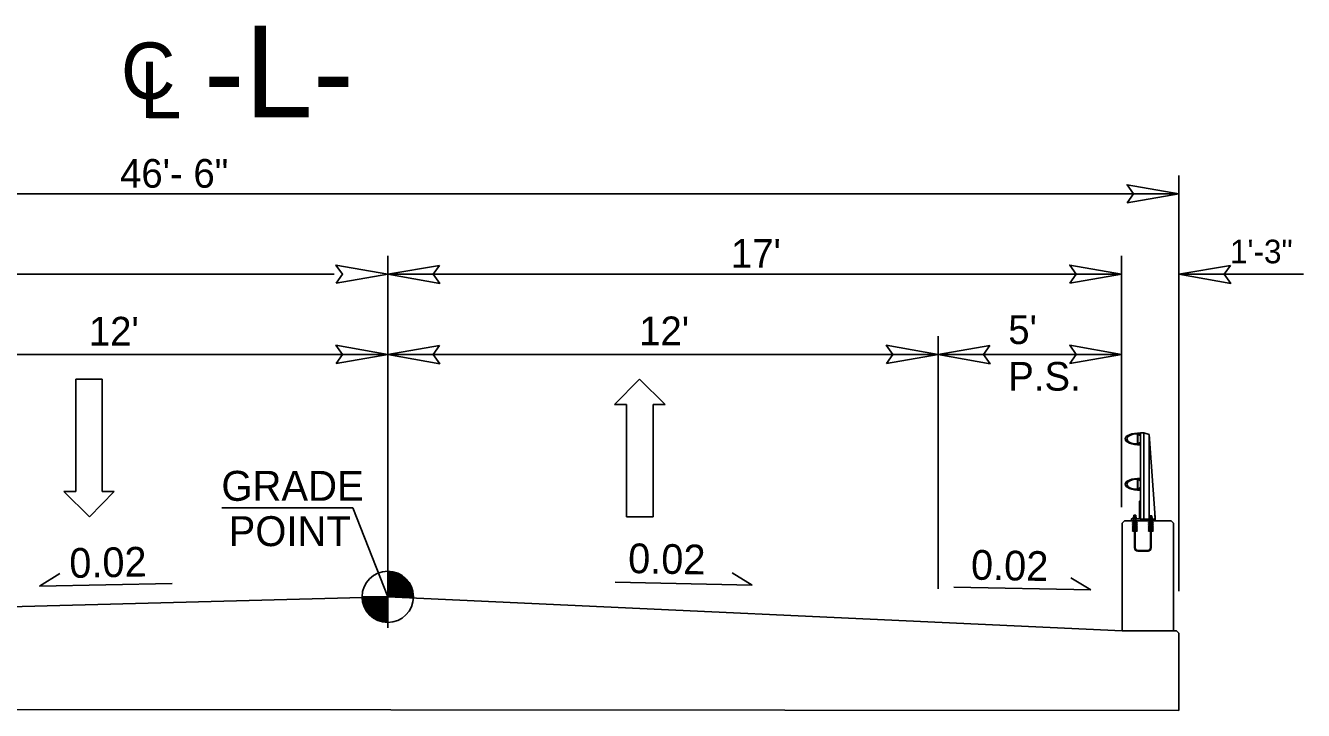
# Model space of a CAD drawing. Extents: x 1733676 to 1734289, y 540979 to 541226.
# Drawn here: x 1733769.65 to 1733797.52, y 541034.32 to 541049.26 of the extents above; entities that cross this region are included whole.
import ezdxf

# ---------------------------------------------------------------- set-up
doc = ezdxf.new("R2010")
doc.units = 0
for name, color, linetype in [('Prop Dimension', 7, 'Continuous'), ('Prop Lane Arrow CELL', 7, 'Continuous'), ('Prop Terminator CELL', 7, 'Continuous'), ('Typical Bridge Rail Two Bar CELL', 7, 'Continuous'), ('Typical Grade Point Symbol CELL', 7, 'Continuous'), ('Typical Pavement Slope CELL', 7, 'Continuous'), ('Typical Pavement Slope Information CELL', 7, 'Continuous'), ('Typical Slope Point Local CELL', 7, 'Continuous'), ('Typical Text Centerline CELL', 7, 'Continuous'), ('Typical Text Grade Point CELL', 7, 'Continuous')]:
    doc.layers.add(name, color=color, linetype=linetype)

msp = doc.modelspace()

# ---------------------------------------------------------------- linework, layer by layer
at = {"layer": 'Prop Dimension'}
for p, q in [((1733794.804, 541036.923), (1733794.804, 541045.985)), ((1733794.804, 541045.585), (1733749.804, 541045.585)), ((1733777.554, 541036.129), (1733777.554, 541044.235)), ((1733793.554, 541038.756), (1733793.554, 541044.235)), ((1733776.387, 541043.835), (1733760.554, 541043.835)), ((1733793.554, 541043.835), (1733777.554, 541043.835)), ((1733794.804, 541043.835), (1733797.519, 541043.835)), ((1733789.554, 541036.979), (1733789.554, 541042.485)), ((1733777.554, 541042.085), (1733765.554, 541042.085)), ((1733789.554, 541042.085), (1733777.554, 541042.085)), ((1733793.554, 541042.085), (1733789.554, 541042.085)), ((1733773.933, 541038.739), (1733776.793, 541038.739)), ((1733777.554, 541036.801), (1733776.793, 541038.739))]:
    msp.add_line(p, q, dxfattribs=at)
at = {"layer": 'Prop Lane Arrow CELL'}
for p, q in [((1733770.75, 541039.095), (1733770.75, 541041.545)), ((1733770.75, 541041.545), (1733771.327, 541041.545)), ((1733771.327, 541041.545), (1733771.327, 541039.095)), ((1733782.497, 541040.994), (1733783.04, 541041.545)), ((1733783.04, 541041.545), (1733783.6, 541040.994)), ((1733782.76, 541040.994), (1733782.497, 541040.994)), ((1733782.76, 541038.544), (1733782.76, 541040.994)), ((1733783.6, 541040.994), (1733783.337, 541040.994)), ((1733783.337, 541040.994), (1733783.337, 541038.544)), ((1733771.047, 541038.544), (1733770.487, 541039.095)), ((1733770.487, 541039.095), (1733770.75, 541039.095)), ((1733771.59, 541039.095), (1733771.047, 541038.544)), ((1733771.327, 541039.095), (1733771.59, 541039.095)), ((1733783.337, 541038.544), (1733782.76, 541038.544))]:
    msp.add_line(p, q, dxfattribs=at)
at = {"layer": 'Prop Terminator CELL'}
for points in [[(1733793.679, 541045.391), (1733794.804, 541045.585), (1733793.673, 541045.785), (1733793.816, 541045.585)], [(1733776.429, 541043.641), (1733777.554, 541043.835), (1733776.423, 541044.035), (1733776.566, 541043.835)], [(1733778.679, 541044.029), (1733777.554, 541043.835), (1733778.685, 541043.635), (1733778.541, 541043.835)], [(1733792.429, 541043.641), (1733793.554, 541043.835), (1733792.423, 541044.035), (1733792.566, 541043.835)], [(1733795.929, 541044.029), (1733794.804, 541043.835), (1733795.935, 541043.635), (1733795.791, 541043.835)], [(1733776.429, 541041.891), (1733777.554, 541042.085), (1733776.423, 541042.285), (1733776.566, 541042.085)], [(1733778.679, 541042.279), (1733777.554, 541042.085), (1733778.685, 541041.885), (1733778.541, 541042.085)], [(1733788.429, 541041.891), (1733789.554, 541042.085), (1733788.423, 541042.285), (1733788.566, 541042.085)], [(1733790.679, 541042.279), (1733789.554, 541042.085), (1733790.685, 541041.885), (1733790.541, 541042.085)], [(1733792.429, 541041.891), (1733793.554, 541042.085), (1733792.423, 541042.285), (1733792.566, 541042.085)]]:
    msp.add_lwpolyline(points, close=True, dxfattribs=at)
at = {"layer": 'Typical Bridge Rail Two Bar CELL'}
for p, q in [((1733793.901, 541040.346), (1733793.901, 541040.244)), ((1733793.964, 541040.377), (1733794.04, 541040.377)), ((1733793.964, 541038.494), (1733793.964, 541040.377)), ((1733794.154, 541040.34), (1733794.04, 541040.377)), ((1733794.04, 541038.494), (1733794.04, 541040.377)), ((1733794.154, 541038.494), (1733794.154, 541040.34)), ((1733794.154, 541040.34), (1733794.285, 541038.531)), ((1733793.901, 541040.141), (1733793.901, 541040.244)), ((1733793.901, 541039.359), (1733793.901, 541039.256)), ((1733793.901, 541039.154), (1733793.901, 541039.256)), ((1733794.154, 541039.476), (1733794.158, 541039.476)), ((1733793.615, 541038.456), (1733793.566, 541038.407)), ((1733793.566, 541038.407), (1733793.566, 541036.062)), ((1733793.615, 541038.456), (1733794.635, 541038.456)), ((1733793.793, 541038.42), (1733793.893, 541038.42)), ((1733793.793, 541038.409), (1733793.893, 541038.409)), ((1733793.793, 541038.375), (1733793.835, 541038.375)), ((1733793.793, 541038.364), (1733793.835, 541038.364)), ((1733793.815, 541038.397), (1733793.835, 541038.397)), ((1733793.815, 541038.386), (1733793.835, 541038.386)), ((1733793.818, 541038.42), (1733793.818, 541038.503)), ((1733793.82, 541038.544), (1733793.82, 541038.58)), ((1733793.82, 541038.58), (1733793.863, 541038.58)), ((1733793.835, 541038.398), (1733793.835, 541037.867)), ((1733793.835, 541038.397), (1733793.851, 541038.397)), ((1733793.851, 541038.398), (1733793.851, 541037.867)), ((1733793.851, 541038.397), (1733793.871, 541038.397)), ((1733793.851, 541038.386), (1733793.871, 541038.386)), ((1733793.851, 541038.375), (1733793.893, 541038.375)), ((1733793.851, 541038.364), (1733793.893, 541038.364)), ((1733793.863, 541038.58), (1733793.863, 541038.544)), ((1733793.865, 541038.42), (1733793.865, 541038.503)), ((1733794.141, 541038.42), (1733794.242, 541038.42)), ((1733794.141, 541038.409), (1733794.242, 541038.409)), ((1733794.141, 541038.375), (1733794.183, 541038.375)), ((1733794.141, 541038.364), (1733794.183, 541038.364)), ((1733794.164, 541038.397), (1733794.183, 541038.397)), ((1733794.164, 541038.386), (1733794.183, 541038.386)), ((1733794.169, 541038.534), (1733794.169, 541038.57)), ((1733794.169, 541038.57), (1733794.212, 541038.57)), ((1733794.169, 541038.41), (1733794.169, 541038.494)), ((1733794.183, 541038.398), (1733794.2, 541038.398)), ((1733794.183, 541038.398), (1733794.183, 541037.867)), ((1733794.2, 541038.398), (1733794.2, 541037.867)), ((1733794.2, 541038.397), (1733794.22, 541038.397)), ((1733794.2, 541038.386), (1733794.22, 541038.386)), ((1733794.2, 541038.375), (1733794.242, 541038.375)), ((1733794.2, 541038.364), (1733794.242, 541038.364)), ((1733794.212, 541038.57), (1733794.212, 541038.534)), ((1733794.213, 541038.41), (1733794.213, 541038.494)), ((1733794.282, 541038.552), (1733794.282, 541038.585)), ((1733794.285, 541038.494), (1733794.285, 541038.531)), ((1733794.684, 541038.407), (1733794.635, 541038.456)), ((1733794.684, 541038.407), (1733794.684, 541036.062)), ((1733793.793, 541038.331), (1733793.835, 541038.331)), ((1733793.793, 541038.319), (1733793.835, 541038.319)), ((1733793.793, 541038.286), (1733793.835, 541038.286)), ((1733793.793, 541038.275), (1733793.835, 541038.275)), ((1733793.793, 541038.242), (1733793.835, 541038.242)), ((1733793.793, 541038.231), (1733793.835, 541038.231)), ((1733793.815, 541038.353), (1733793.835, 541038.353)), ((1733793.815, 541038.342), (1733793.835, 541038.342)), ((1733793.815, 541038.308), (1733793.835, 541038.308)), ((1733793.815, 541038.297), (1733793.835, 541038.297)), ((1733793.815, 541038.264), (1733793.835, 541038.264)), ((1733793.815, 541038.253), (1733793.835, 541038.253)), ((1733793.851, 541038.353), (1733793.871, 541038.353)), ((1733793.851, 541038.342), (1733793.871, 541038.342)), ((1733793.851, 541038.331), (1733793.893, 541038.331)), ((1733793.851, 541038.319), (1733793.893, 541038.319)), ((1733793.851, 541038.308), (1733793.871, 541038.308)), ((1733793.851, 541038.297), (1733793.871, 541038.297)), ((1733793.851, 541038.286), (1733793.893, 541038.286)), ((1733793.851, 541038.275), (1733793.893, 541038.275)), ((1733793.851, 541038.264), (1733793.871, 541038.264)), ((1733793.851, 541038.253), (1733793.871, 541038.253)), ((1733793.851, 541038.242), (1733793.893, 541038.242)), ((1733793.851, 541038.231), (1733793.893, 541038.231)), ((1733794.141, 541038.331), (1733794.183, 541038.331)), ((1733794.141, 541038.319), (1733794.183, 541038.319)), ((1733794.141, 541038.286), (1733794.183, 541038.286)), ((1733794.141, 541038.275), (1733794.183, 541038.275)), ((1733794.141, 541038.242), (1733794.183, 541038.242)), ((1733794.141, 541038.231), (1733794.183, 541038.231)), ((1733794.164, 541038.353), (1733794.183, 541038.353)), ((1733794.164, 541038.342), (1733794.183, 541038.342)), ((1733794.164, 541038.308), (1733794.183, 541038.308)), ((1733794.164, 541038.297), (1733794.183, 541038.297)), ((1733794.164, 541038.264), (1733794.183, 541038.264)), ((1733794.164, 541038.253), (1733794.183, 541038.253)), ((1733794.2, 541038.353), (1733794.22, 541038.353)), ((1733794.2, 541038.342), (1733794.22, 541038.342)), ((1733794.2, 541038.331), (1733794.242, 541038.331)), ((1733794.2, 541038.319), (1733794.242, 541038.319)), ((1733794.2, 541038.308), (1733794.22, 541038.308)), ((1733794.2, 541038.297), (1733794.22, 541038.297)), ((1733794.2, 541038.286), (1733794.242, 541038.286)), ((1733794.2, 541038.275), (1733794.242, 541038.275)), ((1733794.2, 541038.264), (1733794.22, 541038.264)), ((1733794.2, 541038.253), (1733794.22, 541038.253)), ((1733794.2, 541038.242), (1733794.242, 541038.242)), ((1733794.2, 541038.231), (1733794.242, 541038.231)), ((1733793.905, 541037.814), (1733794.13, 541037.814)), ((1733793.905, 541037.797), (1733794.13, 541037.797)), ((1733793.566, 541036.062), (1733794.674, 541036.062)), ((1733794.674, 541036.062), (1733794.755, 541036.062)), ((1733794.804, 541036.009), (1733794.755, 541036.062))]:
    msp.add_line(p, q, dxfattribs=at)
for points in [[(1733793.964, 541040.113), (1733793.964, 541040.162), (1733793.944, 541040.162), (1733793.944, 541040.154), (1733793.946, 541040.154), (1733793.946, 541040.133), (1733793.914, 541040.133), (1733793.91, 541040.165), (1733793.91, 541040.244), (1733793.91, 541040.322), (1733793.914, 541040.354), (1733793.946, 541040.354), (1733793.946, 541040.333), (1733793.944, 541040.333), (1733793.944, 541040.325), (1733793.964, 541040.325), (1733793.964, 541040.374)], [(1733793.964, 541039.126), (1733793.964, 541039.175), (1733793.944, 541039.175), (1733793.944, 541039.167), (1733793.946, 541039.167), (1733793.946, 541039.146), (1733793.914, 541039.146), (1733793.91, 541039.178), (1733793.91, 541039.256), (1733793.91, 541039.335), (1733793.914, 541039.366), (1733793.946, 541039.366), (1733793.946, 541039.346), (1733793.944, 541039.346), (1733793.944, 541039.338), (1733793.964, 541039.338), (1733793.964, 541039.387)], [(1733793.771, 541038.456), (1733793.771, 541038.503), (1733793.946, 541038.503), (1733793.946, 541038.89), (1733793.964, 541038.89), (1733793.964, 541038.494), (1733794.276, 541038.494), (1733794.276, 541038.521), (1733794.285, 541038.521), (1733794.285, 541038.456), (1733794.135, 541038.456), (1733794.135, 541038.482), (1733793.983, 541038.482), (1733793.983, 541038.456), (1733793.771, 541038.456)], [(1733793.793, 541038.42), (1733793.793, 541038.409), (1733793.815, 541038.397), (1733793.815, 541038.386), (1733793.793, 541038.375), (1733793.793, 541038.364), (1733793.815, 541038.353), (1733793.815, 541038.342), (1733793.793, 541038.331), (1733793.793, 541038.319), (1733793.815, 541038.308), (1733793.815, 541038.297), (1733793.793, 541038.286), (1733793.793, 541038.275), (1733793.815, 541038.264), (1733793.815, 541038.253), (1733793.793, 541038.242), (1733793.793, 541038.231)], [(1733793.798, 541038.503), (1733793.798, 541038.511), (1733793.841, 541038.511), (1733793.884, 541038.511), (1733793.884, 541038.503)], [(1733793.81, 541038.511), (1733793.81, 541038.538), (1733793.815, 541038.544), (1733793.868, 541038.544), (1733793.873, 541038.538), (1733793.873, 541038.511), (1733793.81, 541038.511), (1733793.831, 541038.511), (1733793.831, 541038.538), (1733793.826, 541038.544), (1733793.831, 541038.538), (1733793.836, 541038.544), (1733793.847, 541038.544), (1733793.852, 541038.538), (1733793.852, 541038.511), (1733793.852, 541038.538), (1733793.857, 541038.544)], [(1733793.893, 541038.42), (1733793.893, 541038.409), (1733793.871, 541038.397), (1733793.871, 541038.386), (1733793.893, 541038.375), (1733793.893, 541038.364), (1733793.871, 541038.353), (1733793.871, 541038.342), (1733793.893, 541038.331), (1733793.893, 541038.319), (1733793.871, 541038.308), (1733793.871, 541038.297), (1733793.893, 541038.286), (1733793.893, 541038.275), (1733793.871, 541038.264), (1733793.871, 541038.253), (1733793.893, 541038.242), (1733793.893, 541038.231)], [(1733794.141, 541038.42), (1733794.141, 541038.409), (1733794.163, 541038.397), (1733794.163, 541038.386), (1733794.141, 541038.375), (1733794.141, 541038.364), (1733794.163, 541038.353), (1733794.163, 541038.342), (1733794.141, 541038.331), (1733794.141, 541038.319), (1733794.163, 541038.308), (1733794.163, 541038.297), (1733794.141, 541038.286), (1733794.141, 541038.275), (1733794.163, 541038.264), (1733794.163, 541038.253), (1733794.141, 541038.242), (1733794.141, 541038.231)], [(1733794.148, 541038.493), (1733794.148, 541038.502), (1733794.191, 541038.502), (1733794.233, 541038.502), (1733794.233, 541038.493)], [(1733794.159, 541038.502), (1733794.159, 541038.529), (1733794.164, 541038.534), (1733794.217, 541038.534), (1733794.222, 541038.529), (1733794.222, 541038.502), (1733794.159, 541038.502), (1733794.18, 541038.502), (1733794.18, 541038.529), (1733794.175, 541038.534), (1733794.18, 541038.529), (1733794.185, 541038.534), (1733794.196, 541038.534), (1733794.201, 541038.529), (1733794.201, 541038.502), (1733794.201, 541038.529), (1733794.207, 541038.534)], [(1733794.242, 541038.42), (1733794.242, 541038.409), (1733794.22, 541038.397), (1733794.22, 541038.386), (1733794.242, 541038.375), (1733794.242, 541038.364), (1733794.22, 541038.353), (1733794.22, 541038.342), (1733794.242, 541038.331), (1733794.242, 541038.319), (1733794.22, 541038.308), (1733794.22, 541038.297), (1733794.242, 541038.286), (1733794.242, 541038.275), (1733794.22, 541038.264), (1733794.22, 541038.253), (1733794.242, 541038.242), (1733794.242, 541038.231)]]:
    msp.add_lwpolyline(points, dxfattribs=at)
for centre in [(1733793.802, 541038.259), (1733794.233, 541038.259)]:
    msp.add_circle(centre, 0.00834, dxfattribs=at)
for centre, radius, start, end in [((1733793.894, 541040.346), 0.00783, 0, 90), ((1733793.894, 541040.141), 0.00783, 270, 0), ((1733793.894, 541039.359), 0.00783, 0, 90), ((1733793.894, 541039.154), 0.00783, 270, 0), ((1733793.905, 541037.867), 0.07, 180, 270), ((1733793.905, 541037.867), 0.0534, 180, 270), ((1733794.13, 541037.867), 0.0534, 270, 0), ((1733794.13, 541037.867), 0.07, 270, 0)]:
    msp.add_arc(centre, radius, start, end, dxfattribs=at)
for centre, major_axis, ratio, start_param, end_param in [((1733793.965, 541040.244), (-0.334, 0), 0.39036, 4.712404, 6.283584), ((1733793.894, 541040.244), (-0.222, 0), 0.495501, 4.712489, 6.283652), ((1733793.965, 541040.244), (-0.334, 0), 0.39036, 0.000398, 1.570782), ((1733793.894, 541040.244), (-0.222, 0), 0.495501, 0.000467, 1.570696), ((1733793.965, 541039.256), (-0.334, 0), 0.39036, 4.712404, 6.283584), ((1733793.965, 541039.256), (-0.334, 0), 0.39036, 0.000398, 1.570782), ((1733793.894, 541039.256), (-0.222, 0), 0.495501, 4.712489, 6.283652), ((1733793.894, 541039.256), (-0.222, 0), 0.495501, 0.000467, 1.570696)]:
    msp.add_ellipse(centre, major_axis=major_axis, ratio=ratio, start_param=start_param, end_param=end_param, dxfattribs=at)
at = {"layer": 'Typical Grade Point Symbol CELL'}
for p, q in [((1733777.554, 541036.801), (1733777.554, 541037.361)), ((1733776.994, 541036.801), (1733777.554, 541036.801)), ((1733777.553, 541036.242), (1733777.554, 541036.801)), ((1733777.554, 541036.801), (1733777.553, 541036.242)), ((1733778.113, 541036.801), (1733777.554, 541036.801))]:
    msp.add_line(p, q, dxfattribs=at)
for points in [[(1733777.559, 541037.361), (1733777.559, 541037.361), (1733777.559, 541036.801)], [(1733777.57, 541037.361), (1733777.57, 541036.801)], [(1733777.581, 541037.36), (1733777.581, 541036.801)], [(1733777.592, 541037.36), (1733777.592, 541036.801)], [(1733777.604, 541037.358), (1733777.604, 541036.801)], [(1733777.615, 541037.357), (1733777.615, 541036.801)], [(1733777.626, 541037.356), (1733777.626, 541036.801)], [(1733777.637, 541037.355), (1733777.637, 541036.801)], [(1733777.648, 541037.354), (1733777.648, 541036.801)], [(1733777.66, 541037.351), (1733777.66, 541036.801)], [(1733777.671, 541037.349), (1733777.671, 541036.801)], [(1733777.682, 541037.346), (1733777.682, 541036.801)], [(1733777.693, 541037.344), (1733777.693, 541036.801)], [(1733777.704, 541037.34), (1733777.704, 541036.801)], [(1733777.715, 541037.337), (1733777.715, 541036.801)], [(1733777.727, 541037.334), (1733777.727, 541036.801)], [(1733777.738, 541037.33), (1733777.738, 541036.801)], [(1733777.749, 541037.326), (1733777.749, 541036.801)], [(1733777.76, 541037.321), (1733777.76, 541036.801)], [(1733777.771, 541037.316), (1733777.771, 541036.801)], [(1733777.783, 541037.311), (1733777.783, 541036.801)], [(1733777.794, 541037.306), (1733777.794, 541036.801)], [(1733777.805, 541037.301), (1733777.805, 541036.801)], [(1733777.816, 541037.295), (1733777.816, 541036.801)], [(1733777.827, 541037.289), (1733777.827, 541036.801)], [(1733777.839, 541037.283), (1733777.839, 541036.801)], [(1733777.85, 541037.276), (1733777.85, 541036.801)], [(1733777.861, 541037.269), (1733777.861, 541036.801)], [(1733777.872, 541037.262), (1733777.872, 541036.801)], [(1733777.883, 541037.253), (1733777.883, 541036.801)], [(1733777.895, 541037.245), (1733777.895, 541036.801)], [(1733777.906, 541037.237), (1733777.906, 541036.801)], [(1733777.917, 541037.227), (1733777.917, 541036.801)], [(1733777.928, 541037.217), (1733777.928, 541036.801)], [(1733777.939, 541037.207), (1733777.939, 541036.801)], [(1733777.95, 541037.196), (1733777.95, 541036.801)], [(1733777.962, 541037.184), (1733777.962, 541036.801)], [(1733777.973, 541037.172), (1733777.973, 541036.801)], [(1733777.984, 541037.158), (1733777.984, 541036.801)], [(1733777.995, 541037.145), (1733777.995, 541036.801)], [(1733778.006, 541037.13), (1733778.006, 541036.801)], [(1733778.018, 541037.114), (1733778.018, 541036.801)], [(1733778.029, 541037.096), (1733778.029, 541036.801)], [(1733778.04, 541037.078), (1733778.04, 541036.801)], [(1733778.051, 541037.058), (1733778.051, 541036.801)], [(1733778.062, 541037.034), (1733778.062, 541036.801)], [(1733778.074, 541037.008), (1733778.074, 541036.801)], [(1733778.085, 541036.977), (1733778.085, 541036.801)], [(1733776.997, 541036.801), (1733776.997, 541036.741)], [(1733777.008, 541036.801), (1733777.008, 541036.675)], [(1733777.019, 541036.801), (1733777.019, 541036.635)], [(1733777.03, 541036.801), (1733777.03, 541036.601)], [(1733777.042, 541036.801), (1733777.042, 541036.575)], [(1733777.053, 541036.801), (1733777.053, 541036.552)], [(1733777.064, 541036.801), (1733777.064, 541036.531)], [(1733777.075, 541036.801), (1733777.075, 541036.511)], [(1733777.086, 541036.801), (1733777.086, 541036.493)], [(1733777.098, 541036.801), (1733777.098, 541036.477)], [(1733777.109, 541036.801), (1733777.109, 541036.462)], [(1733777.12, 541036.801), (1733777.12, 541036.448)], [(1733777.131, 541036.801), (1733777.131, 541036.435)], [(1733777.142, 541036.801), (1733777.142, 541036.422)], [(1733777.154, 541036.801), (1733777.154, 541036.41)], [(1733777.165, 541036.801), (1733777.165, 541036.399)], [(1733777.176, 541036.801), (1733777.176, 541036.389)], [(1733777.187, 541036.801), (1733777.187, 541036.379)], [(1733777.198, 541036.801), (1733777.198, 541036.369)], [(1733777.209, 541036.801), (1733777.209, 541036.36)], [(1733777.221, 541036.801), (1733777.221, 541036.351)], [(1733777.232, 541036.801), (1733777.232, 541036.344)], [(1733777.243, 541036.801), (1733777.243, 541036.337)], [(1733777.254, 541036.801), (1733777.254, 541036.329)], [(1733777.265, 541036.801), (1733777.265, 541036.322)], [(1733777.277, 541036.801), (1733777.277, 541036.315)], [(1733777.288, 541036.801), (1733777.288, 541036.309)], [(1733777.299, 541036.801), (1733777.299, 541036.303)], [(1733777.31, 541036.801), (1733777.31, 541036.298)], [(1733777.321, 541036.801), (1733777.321, 541036.293)], [(1733777.333, 541036.801), (1733777.333, 541036.288)], [(1733777.344, 541036.801), (1733777.344, 541036.283)], [(1733777.355, 541036.801), (1733777.355, 541036.278)], [(1733777.366, 541036.801), (1733777.366, 541036.274)], [(1733777.377, 541036.801), (1733777.377, 541036.271)], [(1733777.388, 541036.801), (1733777.388, 541036.267)], [(1733777.4, 541036.801), (1733777.4, 541036.264)], [(1733777.411, 541036.801), (1733777.411, 541036.261)], [(1733777.422, 541036.801), (1733777.422, 541036.258)], [(1733777.433, 541036.801), (1733777.433, 541036.256)], [(1733777.444, 541036.801), (1733777.444, 541036.253)], [(1733777.456, 541036.801), (1733777.456, 541036.251)], [(1733777.467, 541036.801), (1733777.467, 541036.249)], [(1733777.478, 541036.801), (1733777.478, 541036.247)], [(1733777.489, 541036.801), (1733777.489, 541036.246)], [(1733777.5, 541036.801), (1733777.5, 541036.245)], [(1733777.512, 541036.801), (1733777.512, 541036.243)], [(1733777.523, 541036.801), (1733777.523, 541036.243)], [(1733777.534, 541036.801), (1733777.534, 541036.242)], [(1733777.545, 541036.801), (1733777.545, 541036.242), (1733777.545, 541036.242)], [(1733778.096, 541036.938), (1733778.096, 541036.801)], [(1733778.107, 541036.881), (1733778.107, 541036.801)]]:
    msp.add_lwpolyline(points, dxfattribs=at)
msp.add_circle((1733777.553, 541036.802), 0.559, dxfattribs=at)
for start, end in [(359.9905, 89.9905), (179.9905, 269.9905)]:
    msp.add_arc((1733777.553, 541036.802), 0.559, start, end, dxfattribs=at)
at = {"layer": 'Typical Pavement Slope CELL'}
for p, q in [((1733777.554, 541036.801), (1733751.054, 541036.102)), ((1733793.566, 541036.062), (1733777.554, 541036.801))]:
    msp.add_line(p, q, dxfattribs=at)
at = {"layer": 'Typical Pavement Slope Information CELL'}
for p, q in [((1733769.956, 541037.036), (1733770.405, 541037.308)), ((1733785.5, 541037.058), (1733785.062, 541037.322)), ((1733769.956, 541037.036), (1733772.851, 541037.094)), ((1733785.5, 541037.058), (1733782.509, 541037.118)), ((1733792.887, 541036.955), (1733789.896, 541037.015)), ((1733792.887, 541036.955), (1733792.45, 541037.219))]:
    msp.add_line(p, q, dxfattribs=at)
at = {"layer": 'Typical Slope Point Local CELL'}
for p, q in [((1733794.804, 541034.324), (1733794.804, 541036.009)), ((1733749.816, 541034.364), (1733794.804, 541034.324))]:
    msp.add_line(p, q, dxfattribs=at)

# ---------------------------------------------------------------- texts
at = {"layer": 'Typical Pavement Slope Information CELL'}
for rotation, p in [(1.1457, (1733770.615, 541037.213)), (358.8543, (1733782.789, 541037.321)), (358.8543, (1733790.265, 541037.178))]:
    msp.add_text('0.02', height=0.6476, rotation=rotation, dxfattribs=at).set_placement(p)
at = {"layer": 'Typical Slope Point Local CELL'}
for s, height, p in [('46\'- 6"', 0.6249, (1733771.715, 541045.722)), ("17'", 0.6249, (1733785.035, 541043.975)), ('1\'-3"', 0.5141, (1733795.916, 541044.074)), ("12'", 0.6249, (1733771.035, 541042.281)), ("12'", 0.6249, (1733783.035, 541042.288)), ("5'", 0.6249, (1733791.083, 541042.313)), ('P.S.', 0.6249, (1733791.083, 541041.297))]:
    msp.add_text(s, height=height, rotation=360, dxfattribs=at).set_placement(p)
at = {"layer": 'Typical Text Centerline CELL'}
for s, height, p in [('-L-', 2, (1733773.54, 541047.257)), ('C', 1.23, (1733771.734, 541047.658))]:
    msp.add_text(s, height=height, dxfattribs=at).set_placement(p)
msp.add_text('L', height=1.231, rotation=359.9469, dxfattribs=at).set_placement((1733772.143, 541047.238))
at = {"layer": 'Typical Text Grade Point CELL'}
for s, p in [('GRADE', (1733773.925, 541038.895)), ('POINT', (1733774.082, 541037.907))]:
    msp.add_text(s, height=0.6525, dxfattribs=at).set_placement(p)

doc.saveas('drawing.dxf')
